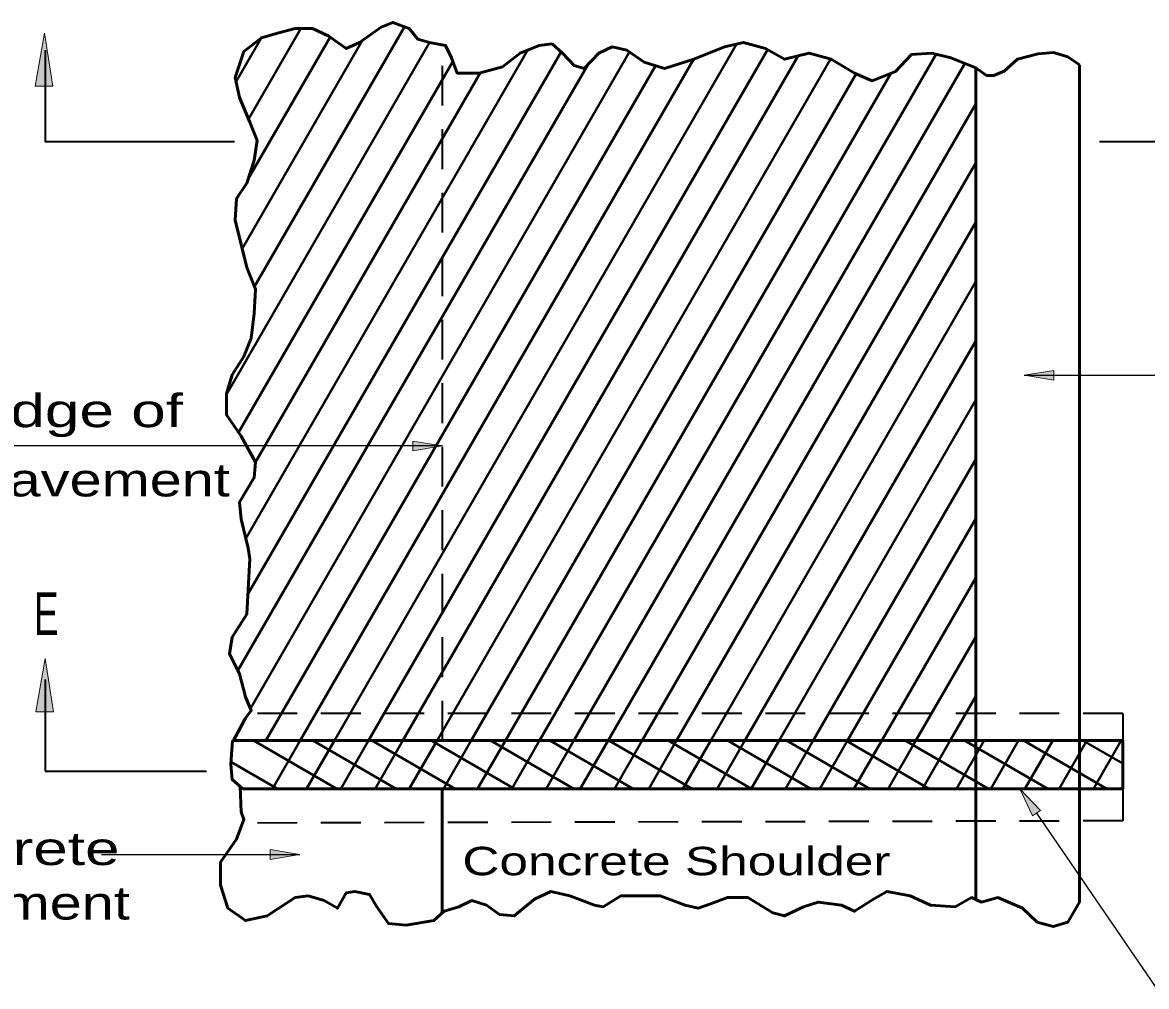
# Model space of a CAD drawing. Extents: x 14 to 49.3, y 28 to 50.
# Drawn here: x 18.004 to 22.747, y 32.826 to 36.894 of the extents above; entities that cross this region are included whole.
import ezdxf

# ---------------------------------------------------------------- set-up
doc = ezdxf.new("R2010")
doc.units = 0
doc.header["$LTSCALE"] = 0.056
doc.linetypes.add('MEDIUM_DASHED', pattern=[4.5, 3, -1.5])
for name, color, linetype, lineweight in [('1', 7, 'Continuous', 35), ('2', 7, 'MEDIUM_DASHED', 35), ('3', 7, 'Continuous', 13), ('5', 7, 'Continuous', 35)]:
    doc.layers.add(name, color=color, linetype=linetype, lineweight=lineweight)

msp = doc.modelspace()

# ---------------------------------------------------------------- hatches: boundary and pattern name
at = {"layer": '3'}
for points in [[(18.13267, 36.62458), (18.05783, 36.62525), (18.09667, 36.84925), (18.09667, 36.84925)], [(22.35575, 35.384), (22.35575, 35.42567), (22.23075, 35.40483), (22.23075, 35.40483)], [(19.65133, 35.12767), (19.65133, 35.086), (19.77633, 35.10683), (19.77633, 35.10683)], [(18.13525, 33.98467), (18.06042, 33.98533), (18.09925, 34.20933), (18.09925, 34.20933)], [(22.26508, 33.5455), (22.2995, 33.569), (22.21167, 33.66042), (22.21167, 33.66042)], [(19.04933, 33.40375), (19.04933, 33.36208), (19.17433, 33.38292), (19.17433, 33.38292)]]:
    msp.add_hatch(color=256, dxfattribs=at).paths.add_polyline_path(points)

# ---------------------------------------------------------------- linework, layer by layer
at = {"layer": '1', "lineweight": 40}
for p, q in [((18.95783, 36.486), (19.17842, 36.86792)), ((18.98325, 35.77983), (19.61567, 36.87525)), ((18.8645, 35.32417), (19.722, 36.80958)), ((18.90508, 36.6445), (19.011, 36.828)), ((18.93058, 35.93875), (19.43892, 36.81917)), ((18.95692, 36.23425), (19.30175, 36.8315)), ((18.94667, 34.71658), (20.13683, 36.77792)), ((18.95517, 34.48133), (20.27633, 36.76958)), ((18.9655, 33.99917), (20.56483, 36.76933)), ((19.32017, 33.86342), (21.01708, 36.80258)), ((19.4645, 33.86342), (21.14767, 36.77883)), ((20.18617, 33.86342), (21.85867, 36.76025)), ((18.91317, 34.15858), (20.38925, 36.71517)), ((18.91575, 35.16292), (19.81983, 36.72892)), ((19.03142, 33.86342), (20.67558, 36.71117)), ((19.17575, 33.86342), (20.8355, 36.73817)), ((19.60883, 33.86342), (21.27708, 36.75292)), ((19.75317, 33.86342), (21.4135, 36.73933)), ((20.3305, 33.86342), (21.9805, 36.72125)), ((18.98775, 35.03775), (19.93708, 36.682)), ((19.8975, 33.86342), (21.522, 36.67725)), ((20.04183, 33.86342), (21.66733, 36.679)), ((20.47483, 33.86342), (22.02642, 36.55083)), ((20.61917, 33.86342), (22.02642, 36.30083)), ((18.9075, 36.14875), (18.91358, 36.15925)), ((20.7635, 33.86342), (22.02642, 36.05083)), ((20.90783, 33.86342), (22.02642, 35.80083)), ((21.05217, 33.86342), (22.02642, 35.55083)), ((21.1965, 33.86342), (22.02642, 35.30083)), ((21.34083, 33.86342), (22.02642, 35.05083)), ((21.48517, 33.86342), (22.02642, 34.80083)), ((21.6295, 33.86342), (22.02642, 34.55083)), ((21.77383, 33.86342), (22.02642, 34.30083)), ((21.91817, 33.86342), (22.02642, 34.05083)), ((18.97842, 33.86342), (19.33008, 33.66042)), ((19.05858, 33.66042), (19.17575, 33.86342)), ((19.20292, 33.66042), (19.32017, 33.86342)), ((19.22842, 33.86342), (19.58008, 33.66042)), ((19.34725, 33.66042), (19.4645, 33.86342)), ((19.47842, 33.86342), (19.83008, 33.66042)), ((19.49158, 33.66042), (19.60883, 33.86342)), ((19.63592, 33.66042), (19.75317, 33.86342)), ((19.72842, 33.86342), (20.08008, 33.66042)), ((19.78025, 33.66042), (19.8975, 33.86342)), ((19.92458, 33.66042), (20.04183, 33.86342)), ((19.97842, 33.86342), (20.33008, 33.66042)), ((20.06892, 33.66042), (20.18617, 33.86342)), ((20.21325, 33.66042), (20.3305, 33.86342)), ((20.22842, 33.86342), (20.58008, 33.66042)), ((20.35758, 33.66042), (20.47483, 33.86342)), ((20.47842, 33.86342), (20.83008, 33.66042)), ((20.50192, 33.66042), (20.61917, 33.86342)), ((20.64625, 33.66042), (20.7635, 33.86342)), ((20.72842, 33.86342), (21.08008, 33.66042)), ((20.79058, 33.66042), (20.90783, 33.86342)), ((20.93492, 33.66042), (21.05217, 33.86342)), ((20.97842, 33.86342), (21.33008, 33.66042)), ((21.07933, 33.66042), (21.1965, 33.86342)), ((21.22367, 33.66042), (21.34083, 33.86342)), ((21.22842, 33.86342), (21.58008, 33.66042)), ((21.368, 33.66042), (21.48517, 33.86342)), ((21.47842, 33.86342), (21.83008, 33.66042)), ((21.51233, 33.66042), (21.6295, 33.86342)), ((21.65667, 33.66042), (21.77383, 33.86342)), ((21.72842, 33.86342), (22.08008, 33.66042)), ((21.801, 33.66042), (21.91817, 33.86342)), ((21.94533, 33.66042), (22.0625, 33.86342)), ((21.97842, 33.86342), (22.33008, 33.66042)), ((22.08967, 33.66042), (22.20692, 33.86342)), ((22.22842, 33.86342), (22.58008, 33.66042)), ((22.234, 33.66042), (22.35125, 33.86342)), ((22.37833, 33.66042), (22.49558, 33.86342)), ((22.47842, 33.86342), (22.64692, 33.76617)), ((22.52267, 33.66042), (22.63992, 33.86342)), ((18.88367, 33.77383), (19.08008, 33.66042))]:
    msp.add_line(p, q, dxfattribs=at)
at = {"layer": '1', "lineweight": 53}
for p, q in [((22.02642, 33.193), (22.02642, 36.70275)), ((22.02642, 33.86342), (18.88975, 33.86342)), ((19.7745, 33.66042), (19.7745, 33.13558))]:
    msp.add_line(p, q, dxfattribs=at)
for points in [[(18.89375, 33.86342), (18.94458, 33.95783), (18.96925, 33.99017), (18.94458, 34.04842), (18.91992, 34.14542), (18.87683, 34.2295), (18.88917, 34.30058), (18.95075, 34.39758), (18.96308, 34.63042), (18.95692, 34.67567), (18.92608, 34.7985), (18.91992, 34.86967), (18.98158, 34.97308), (18.98775, 35.03775), (18.92608, 35.14767), (18.8645, 35.23825), (18.8645, 35.32875), (18.88917, 35.40658), (18.93842, 35.48425), (18.96925, 35.56183), (18.98158, 35.66525), (18.98775, 35.76875), (18.95075, 35.85933), (18.92608, 35.95633), (18.90142, 36.05975), (18.90758, 36.15033), (18.95075, 36.215), (18.98158, 36.312), (18.99392, 36.39583), (18.96308, 36.47342), (18.91992, 36.57692), (18.90142, 36.661), (18.93842, 36.77092), (19.01242, 36.82908), (19.08017, 36.8485), (19.15417, 36.86792), (19.22817, 36.86792), (19.29592, 36.83558), (19.36992, 36.78383), (19.42533, 36.80967)], [(19.42533, 36.80967), (19.51783, 36.87433), (19.56708, 36.89375), (19.63492, 36.86792), (19.67192, 36.82267), (19.72125, 36.80967), (19.789, 36.79675), (19.81367, 36.745), (19.83833, 36.68042), (19.93075, 36.68042), (20.02942, 36.70625), (20.10333, 36.76442), (20.1835, 36.79675), (20.23892, 36.80325), (20.28208, 36.76442), (20.33142, 36.71275), (20.37458, 36.69975), (20.43617, 36.76442), (20.49167, 36.79033), (20.55333, 36.77733), (20.62725, 36.72567), (20.71358, 36.69975), (20.83683, 36.73858), (20.96625, 36.79033), (21.04642, 36.80967), (21.13883, 36.78383), (21.219, 36.73858), (21.32375, 36.76442), (21.41617, 36.73858), (21.51483, 36.68042), (21.58875, 36.64808), (21.68742, 36.68683), (21.75517, 36.758), (21.8415, 36.76442), (21.92158, 36.745), (22.02642, 36.70275)], [(22.02642, 36.70275), (22.07175, 36.67067), (22.10217, 36.67067), (22.14567, 36.68892), (22.20217, 36.73908), (22.28908, 36.76192), (22.35433, 36.7665), (22.41517, 36.74825), (22.464, 36.71558)], [(21.16967, 33.13667), (21.219, 33.12375), (21.29908, 33.1625), (21.36075, 33.18192), (21.45933, 33.169), (21.51483, 33.14308), (21.59492, 33.19483), (21.65042, 33.22717), (21.749, 33.20775), (21.83533, 33.169), (21.94008, 33.1625), (22.00792, 33.20133), (22.05108, 33.18192), (22.11883, 33.20133), (22.22367, 33.15608), (22.28525, 33.09783), (22.35308, 33.07842), (22.41467, 33.09783), (22.464, 33.18192), (22.464, 36.71558)], [(18.93383, 33.66042), (18.88917, 33.69925), (18.883, 33.76392), (18.88975, 33.86342)], [(18.93383, 33.66042), (22.64692, 33.66042), (22.64692, 33.86342), (22.02642, 33.86342)], [(18.92283, 33.66992), (18.92608, 33.56342), (18.93842, 33.53108), (18.90758, 33.447), (18.83983, 33.35), (18.83983, 33.253), (18.87067, 33.15608), (18.94458, 33.10433), (19.03708, 33.12375), (19.15417, 33.20133), (19.20967, 33.20775), (19.27742, 33.18833), (19.33292, 33.15608), (19.36992, 33.22067), (19.40683, 33.22717), (19.4685, 33.21425), (19.49933, 33.1625), (19.54867, 33.09142), (19.62258, 33.08492), (19.73967, 33.10433), (19.78283, 33.14308), (19.8445, 33.1625), (19.9, 33.18833), (19.96158, 33.169), (20.01708, 33.13017), (20.07867, 33.12375), (20.165, 33.19483), (20.23283, 33.22717), (20.31292, 33.20775), (20.41767, 33.169), (20.45467, 33.1625), (20.52867, 33.20775), (20.60875, 33.20775), (20.69508, 33.20775), (20.79983, 33.169), (20.85533, 33.15608), (20.91075, 33.17542), (20.97858, 33.20133), (21.06492, 33.20133), (21.16967, 33.13667)]]:
    msp.add_lwpolyline(points, dxfattribs=at)
at = {"layer": '2'}
for p, q in [((19.77633, 33.86342), (19.77633, 36.79917)), ((22.64692, 33.97725), (18.99392, 33.97725)), ((22.64692, 33.97725), (22.64692, 33.86342)), ((22.64692, 33.66042), (22.64692, 33.52467)), ((22.64692, 33.52467), (18.93267, 33.51542))]:
    msp.add_line(p, q, dxfattribs=at)
at = {"layer": '3', "lineweight": 25}
for p, q in [((22.23075, 35.40483), (23.81375, 35.40483)), ((19.77633, 35.10683), (17.71825, 35.10683)), ((18.33708, 33.38292), (19.17433, 33.38292))]:
    msp.add_line(p, q, dxfattribs=at)
at = {"layer": '3'}
for points in [[(18.13267, 36.62458), (18.05783, 36.62525), (18.09667, 36.84925), (18.09667, 36.84925)], [(22.35575, 35.384), (22.35575, 35.42567), (22.23075, 35.40483), (22.23075, 35.40483)], [(19.65133, 35.12767), (19.65133, 35.086), (19.77633, 35.10683), (19.77633, 35.10683)], [(18.13525, 33.98467), (18.06042, 33.98533), (18.09925, 34.20933), (18.09925, 34.20933)], [(22.26508, 33.5455), (22.2995, 33.569), (22.21167, 33.66042), (22.21167, 33.66042)], [(19.04933, 33.40375), (19.04933, 33.36208), (19.17433, 33.38292), (19.17433, 33.38292)]]:
    msp.add_lwpolyline(points, close=True, dxfattribs=at)
at = {"layer": '3', "lineweight": 25}
msp.add_lwpolyline([(22.28233, 33.55725), (22.783, 32.82575), (23.19808, 32.82575)], dxfattribs=at)
at = {"layer": '5'}
for p, q in [((22.5485, 36.39083), (23.22925, 36.39083)), ((18.09933, 34.121), (18.09933, 33.73483)), ((18.09933, 33.73483), (18.78008, 33.73483))]:
    msp.add_line(p, q, dxfattribs=at)
msp.add_lwpolyline([(18.09933, 36.777), (18.09933, 36.39083), (18.89883, 36.39083)], dxfattribs=at)

# ---------------------------------------------------------------- texts
at = {"layer": '3'}
for s, height, width, p in [('Edge of', 0.14, 1.4, (17.77775, 35.18608)), ('Pavement', 0.14, 1.3, (17.78317, 34.89392)), ('Concrete', 0.14, 1.4, (17.35017, 33.33833)), ('Concrete Shoulder', 0.12, 1.35, (19.86, 33.29517)), ('Pavement', 0.14, 1.3, (17.36117, 33.10833))]:
    msp.add_text(s, height=height, dxfattribs=dict(at, width=width)).set_placement(p)
at = {"layer": '5', "width": 0.65}
msp.add_text('E', height=0.18, dxfattribs=at).set_placement((18.05192, 34.30875))

doc.saveas('drawing.dxf')
